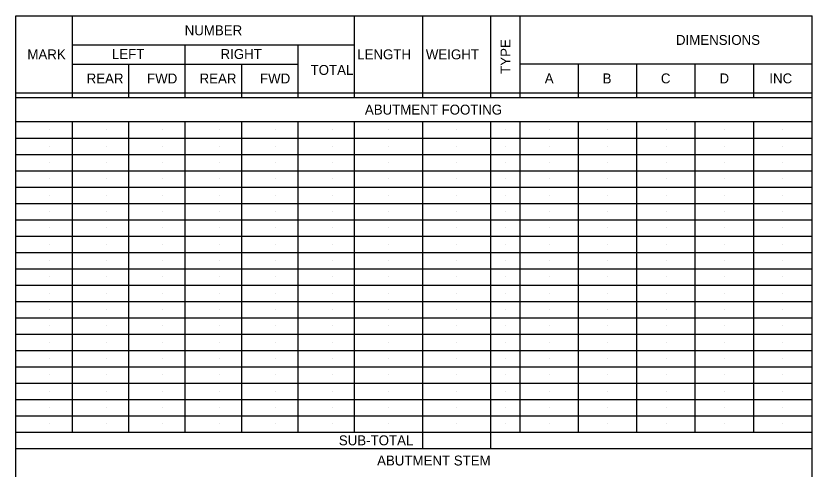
# Model space of a CAD drawing. Extents: x -18.5 to 33.3, y 0.6 to 37.5.
# Drawn here: x -18.5 to -4.86, y 12.95 to 20.71 of the extents above; entities that cross this region are included whole.
import ezdxf

# ---------------------------------------------------------------- set-up
doc = ezdxf.new("R2010")
doc.units = 0
doc.layers.add('BR_X_Beam_Centerline', color=7, linetype='Continuous')

msp = doc.modelspace()

# ---------------------------------------------------------------- linework, layer by layer
at = {"layer": 'BR_X_Beam_Centerline'}
for p, q in [((-18.496, 20.715), (-4.862, 20.715)), ((-18.496, 7.291), (-18.496, 20.715)), ((-17.529, 19.315), (-17.529, 20.715)), ((-12.696, 19.314), (-12.696, 20.715)), ((-11.529, 19.315), (-11.529, 20.715)), ((-10.362, 19.315), (-10.362, 20.715)), ((-9.862, 19.315), (-9.862, 20.715)), ((-4.862, 7.291), (-4.862, 20.715)), ((-17.529, 20.221), (-12.696, 20.221)), ((-15.596, 19.315), (-15.596, 20.221)), ((-13.662, 19.315), (-13.662, 20.221)), ((-17.529, 19.889), (-13.662, 19.888)), ((-16.563, 19.315), (-16.563, 19.889)), ((-14.629, 19.315), (-14.629, 19.888)), ((-9.862, 19.891), (-4.862, 19.891)), ((-8.862, 19.314), (-8.862, 19.891)), ((-7.862, 19.314), (-7.862, 19.891)), ((-6.862, 19.314), (-6.862, 19.891)), ((-5.862, 19.315), (-5.862, 19.891)), ((-5.862, 19.314), (-5.862, 19.891)), ((-16.946, 19.643), (-16.946, 19.643)), ((-15.979, 19.643), (-15.979, 19.643)), ((-15.012, 19.643), (-15.012, 19.643)), ((-14.046, 19.643), (-14.046, 19.643)), ((-18.496, 19.397), (-4.862, 19.397)), ((-18.496, 19.315), (-4.862, 19.315)), ((-11.279, 19.109), (-11.279, 19.109)), ((-18.496, 18.903), (-4.862, 18.903)), ((-17.529, 13.583), (-17.529, 18.903)), ((-16.562, 13.583), (-16.563, 18.903)), ((-15.596, 13.583), (-15.596, 18.903)), ((-14.629, 13.583), (-14.629, 18.903)), ((-13.662, 13.583), (-13.662, 18.903)), ((-12.696, 13.583), (-12.696, 18.903)), ((-11.529, 13.303), (-11.529, 18.903)), ((-10.362, 13.303), (-10.362, 18.903)), ((-9.862, 13.583), (-9.862, 18.903)), ((-8.862, 13.583), (-8.862, 18.903)), ((-7.862, 13.583), (-7.862, 18.903)), ((-6.862, 13.583), (-6.862, 18.903)), ((-5.862, 13.583), (-5.862, 18.903)), ((-5.862, 13.583), (-5.862, 18.903)), ((-17.913, 18.763), (-17.913, 18.763)), ((-16.946, 18.763), (-16.946, 18.763)), ((-15.979, 18.763), (-15.979, 18.763)), ((-15.012, 18.763), (-15.012, 18.763)), ((-14.046, 18.763), (-14.046, 18.763)), ((-13.079, 18.763), (-13.079, 18.763)), ((-12.112, 18.763), (-12.112, 18.763)), ((-10.946, 18.763), (-10.946, 18.763)), ((-10.112, 18.763), (-10.112, 18.763)), ((-9.362, 18.763), (-9.362, 18.763)), ((-8.362, 18.763), (-8.362, 18.763)), ((-7.362, 18.763), (-7.362, 18.763)), ((-6.362, 18.763), (-6.362, 18.763)), ((-5.362, 18.763), (-5.362, 18.763)), ((-18.496, 18.623), (-4.862, 18.623)), ((-17.913, 18.483), (-17.913, 18.483)), ((-16.946, 18.483), (-16.946, 18.483)), ((-15.979, 18.483), (-15.979, 18.483)), ((-15.012, 18.483), (-15.012, 18.483)), ((-14.046, 18.483), (-14.046, 18.483)), ((-13.079, 18.483), (-13.079, 18.483)), ((-12.112, 18.483), (-12.112, 18.483)), ((-10.946, 18.483), (-10.946, 18.483)), ((-10.112, 18.483), (-10.112, 18.483)), ((-9.362, 18.483), (-9.362, 18.483)), ((-8.362, 18.483), (-8.362, 18.483)), ((-7.362, 18.483), (-7.362, 18.483)), ((-6.362, 18.483), (-6.362, 18.483)), ((-5.362, 18.483), (-5.362, 18.483)), ((-18.496, 18.343), (-4.862, 18.343)), ((-17.913, 18.203), (-17.913, 18.203)), ((-16.946, 18.203), (-16.946, 18.203)), ((-15.979, 18.203), (-15.979, 18.203)), ((-15.012, 18.203), (-15.012, 18.203)), ((-14.046, 18.203), (-14.046, 18.203)), ((-13.079, 18.203), (-13.079, 18.203)), ((-12.112, 18.203), (-12.112, 18.203)), ((-10.946, 18.203), (-10.946, 18.203)), ((-10.112, 18.203), (-10.112, 18.203)), ((-9.362, 18.203), (-9.362, 18.203)), ((-8.362, 18.203), (-8.362, 18.203)), ((-7.362, 18.203), (-7.362, 18.203)), ((-6.362, 18.203), (-6.362, 18.203)), ((-5.362, 18.203), (-5.362, 18.203)), ((-18.496, 18.063), (-4.862, 18.063)), ((-17.913, 17.923), (-17.913, 17.923)), ((-16.946, 17.923), (-16.946, 17.923)), ((-15.979, 17.923), (-15.979, 17.923)), ((-15.012, 17.923), (-15.012, 17.923)), ((-14.046, 17.923), (-14.046, 17.923)), ((-13.079, 17.923), (-13.079, 17.923)), ((-12.112, 17.923), (-12.112, 17.923)), ((-10.946, 17.923), (-10.946, 17.923)), ((-10.112, 17.923), (-10.112, 17.923)), ((-9.362, 17.923), (-9.362, 17.923)), ((-8.362, 17.923), (-8.362, 17.923)), ((-7.362, 17.923), (-7.362, 17.923)), ((-6.362, 17.923), (-6.362, 17.923)), ((-5.362, 17.923), (-5.362, 17.923)), ((-18.496, 17.783), (-4.862, 17.783)), ((-17.913, 17.643), (-17.913, 17.643)), ((-16.946, 17.643), (-16.946, 17.643)), ((-15.979, 17.643), (-15.979, 17.643)), ((-15.012, 17.643), (-15.012, 17.643)), ((-14.046, 17.643), (-14.046, 17.643)), ((-13.079, 17.643), (-13.079, 17.643)), ((-12.112, 17.643), (-12.112, 17.643)), ((-10.946, 17.643), (-10.946, 17.643)), ((-10.112, 17.643), (-10.112, 17.643)), ((-9.362, 17.643), (-9.362, 17.643)), ((-8.362, 17.643), (-8.362, 17.643)), ((-7.362, 17.643), (-7.362, 17.643)), ((-6.362, 17.643), (-6.362, 17.643)), ((-5.362, 17.643), (-5.362, 17.643)), ((-18.496, 17.503), (-4.862, 17.503)), ((-17.913, 17.363), (-17.913, 17.363)), ((-16.946, 17.363), (-16.946, 17.363)), ((-15.979, 17.363), (-15.979, 17.363)), ((-15.012, 17.363), (-15.012, 17.363)), ((-14.046, 17.363), (-14.046, 17.363)), ((-13.079, 17.363), (-13.079, 17.363)), ((-12.112, 17.363), (-12.112, 17.363)), ((-10.946, 17.363), (-10.946, 17.363)), ((-10.112, 17.363), (-10.112, 17.363)), ((-9.362, 17.363), (-9.362, 17.363)), ((-8.362, 17.363), (-8.362, 17.363)), ((-7.362, 17.363), (-7.362, 17.363)), ((-6.362, 17.363), (-6.362, 17.363)), ((-5.362, 17.363), (-5.362, 17.363)), ((-18.496, 17.223), (-4.862, 17.223)), ((-17.913, 17.083), (-17.913, 17.083)), ((-16.946, 17.083), (-16.946, 17.083)), ((-15.979, 17.083), (-15.979, 17.083)), ((-15.012, 17.083), (-15.012, 17.083)), ((-14.046, 17.083), (-14.046, 17.083)), ((-13.079, 17.083), (-13.079, 17.083)), ((-12.112, 17.083), (-12.112, 17.083)), ((-10.946, 17.083), (-10.946, 17.083)), ((-10.112, 17.083), (-10.112, 17.083)), ((-9.362, 17.083), (-9.362, 17.083)), ((-8.362, 17.083), (-8.362, 17.083)), ((-7.362, 17.083), (-7.362, 17.083)), ((-6.362, 17.083), (-6.362, 17.083)), ((-5.362, 17.083), (-5.362, 17.083)), ((-18.496, 16.943), (-4.862, 16.943)), ((-17.913, 16.803), (-17.913, 16.803)), ((-16.946, 16.803), (-16.946, 16.803)), ((-15.979, 16.803), (-15.979, 16.803)), ((-15.012, 16.803), (-15.012, 16.803)), ((-14.046, 16.803), (-14.046, 16.803)), ((-13.079, 16.803), (-13.079, 16.803)), ((-12.112, 16.803), (-12.112, 16.803)), ((-10.946, 16.803), (-10.946, 16.803)), ((-10.112, 16.803), (-10.112, 16.803)), ((-9.362, 16.803), (-9.362, 16.803)), ((-8.362, 16.803), (-8.362, 16.803)), ((-7.362, 16.803), (-7.362, 16.803)), ((-6.362, 16.803), (-6.362, 16.803)), ((-5.362, 16.803), (-5.362, 16.803)), ((-18.496, 16.663), (-4.862, 16.663)), ((-17.913, 16.523), (-17.913, 16.523)), ((-16.946, 16.523), (-16.946, 16.523)), ((-15.979, 16.523), (-15.979, 16.523)), ((-15.012, 16.523), (-15.012, 16.523)), ((-14.046, 16.523), (-14.046, 16.523)), ((-13.079, 16.523), (-13.079, 16.523)), ((-12.112, 16.523), (-12.112, 16.523)), ((-10.946, 16.523), (-10.946, 16.523)), ((-10.112, 16.523), (-10.112, 16.523)), ((-9.362, 16.523), (-9.362, 16.523)), ((-8.362, 16.523), (-8.362, 16.523)), ((-7.362, 16.523), (-7.362, 16.523)), ((-6.362, 16.523), (-6.362, 16.523)), ((-5.362, 16.523), (-5.362, 16.523)), ((-18.496, 16.383), (-4.862, 16.383)), ((-17.913, 16.243), (-17.913, 16.243)), ((-16.946, 16.243), (-16.946, 16.243)), ((-15.979, 16.243), (-15.979, 16.243)), ((-15.012, 16.243), (-15.012, 16.243)), ((-14.046, 16.243), (-14.046, 16.243)), ((-13.079, 16.243), (-13.079, 16.243)), ((-12.112, 16.243), (-12.112, 16.243)), ((-10.946, 16.243), (-10.946, 16.243)), ((-10.112, 16.243), (-10.112, 16.243)), ((-9.362, 16.243), (-9.362, 16.243)), ((-8.362, 16.243), (-8.362, 16.243)), ((-7.362, 16.243), (-7.362, 16.243)), ((-6.362, 16.243), (-6.362, 16.243)), ((-5.362, 16.243), (-5.362, 16.243)), ((-18.496, 16.103), (-4.862, 16.103)), ((-17.913, 15.963), (-17.913, 15.963)), ((-16.946, 15.963), (-16.946, 15.963)), ((-15.979, 15.963), (-15.979, 15.963)), ((-15.012, 15.963), (-15.012, 15.963)), ((-14.046, 15.963), (-14.046, 15.963)), ((-13.079, 15.963), (-13.079, 15.963)), ((-12.112, 15.963), (-12.112, 15.963)), ((-10.946, 15.963), (-10.946, 15.963)), ((-10.112, 15.963), (-10.112, 15.963)), ((-9.362, 15.963), (-9.362, 15.963)), ((-8.362, 15.963), (-8.362, 15.963)), ((-7.362, 15.963), (-7.362, 15.963)), ((-6.362, 15.963), (-6.362, 15.963)), ((-5.362, 15.963), (-5.362, 15.963)), ((-18.496, 15.823), (-4.862, 15.823)), ((-17.913, 15.683), (-17.913, 15.683)), ((-16.946, 15.683), (-16.946, 15.683)), ((-15.979, 15.683), (-15.979, 15.683)), ((-15.012, 15.683), (-15.012, 15.683)), ((-14.046, 15.683), (-14.046, 15.683)), ((-13.079, 15.683), (-13.079, 15.683)), ((-12.112, 15.683), (-12.112, 15.683)), ((-10.946, 15.683), (-10.946, 15.683)), ((-10.112, 15.683), (-10.112, 15.683)), ((-9.362, 15.683), (-9.362, 15.683)), ((-8.362, 15.683), (-8.362, 15.683)), ((-7.362, 15.683), (-7.362, 15.683)), ((-6.362, 15.683), (-6.362, 15.683)), ((-5.362, 15.683), (-5.362, 15.683)), ((-18.496, 15.543), (-4.862, 15.543)), ((-17.913, 15.403), (-17.913, 15.403)), ((-16.946, 15.403), (-16.946, 15.403)), ((-15.979, 15.403), (-15.979, 15.403)), ((-15.012, 15.403), (-15.012, 15.403)), ((-14.046, 15.403), (-14.046, 15.403)), ((-13.079, 15.403), (-13.079, 15.403)), ((-12.112, 15.403), (-12.112, 15.403)), ((-10.946, 15.403), (-10.946, 15.403)), ((-10.112, 15.403), (-10.112, 15.403)), ((-9.362, 15.403), (-9.362, 15.403)), ((-8.362, 15.403), (-8.362, 15.403)), ((-7.362, 15.403), (-7.362, 15.403)), ((-6.362, 15.403), (-6.362, 15.403)), ((-5.362, 15.403), (-5.362, 15.403)), ((-18.496, 15.263), (-4.862, 15.263)), ((-17.913, 15.123), (-17.913, 15.123)), ((-16.946, 15.123), (-16.946, 15.123)), ((-15.979, 15.123), (-15.979, 15.123)), ((-15.012, 15.123), (-15.012, 15.123)), ((-14.046, 15.123), (-14.046, 15.123)), ((-13.079, 15.123), (-13.079, 15.123)), ((-12.112, 15.123), (-12.112, 15.123)), ((-10.946, 15.123), (-10.946, 15.123)), ((-10.112, 15.123), (-10.112, 15.123)), ((-9.362, 15.123), (-9.362, 15.123)), ((-8.362, 15.123), (-8.362, 15.123)), ((-7.362, 15.123), (-7.362, 15.123)), ((-6.362, 15.123), (-6.362, 15.123)), ((-5.362, 15.123), (-5.362, 15.123)), ((-18.496, 14.983), (-4.862, 14.983)), ((-17.913, 14.843), (-17.913, 14.843)), ((-16.946, 14.843), (-16.946, 14.843)), ((-15.979, 14.843), (-15.979, 14.843)), ((-15.012, 14.843), (-15.012, 14.843)), ((-14.046, 14.843), (-14.046, 14.843)), ((-13.079, 14.843), (-13.079, 14.843)), ((-12.112, 14.843), (-12.112, 14.843)), ((-10.946, 14.843), (-10.946, 14.843)), ((-10.112, 14.843), (-10.112, 14.843)), ((-9.362, 14.843), (-9.362, 14.843)), ((-8.362, 14.843), (-8.362, 14.843)), ((-7.362, 14.843), (-7.362, 14.843)), ((-6.362, 14.843), (-6.362, 14.843)), ((-5.362, 14.843), (-5.362, 14.843)), ((-18.496, 14.703), (-4.862, 14.703)), ((-17.913, 14.563), (-17.913, 14.563)), ((-16.946, 14.563), (-16.946, 14.563)), ((-15.979, 14.563), (-15.979, 14.563)), ((-15.012, 14.563), (-15.012, 14.563)), ((-14.046, 14.563), (-14.046, 14.563)), ((-13.079, 14.563), (-13.079, 14.563)), ((-12.112, 14.563), (-12.112, 14.563)), ((-10.946, 14.563), (-10.946, 14.563)), ((-10.112, 14.563), (-10.112, 14.563)), ((-9.362, 14.563), (-9.362, 14.563)), ((-8.362, 14.563), (-8.362, 14.563)), ((-7.362, 14.563), (-7.362, 14.563)), ((-6.362, 14.563), (-6.362, 14.563)), ((-5.362, 14.563), (-5.362, 14.563)), ((-18.496, 14.423), (-4.862, 14.423)), ((-17.913, 14.283), (-17.913, 14.283)), ((-16.946, 14.283), (-16.946, 14.283)), ((-15.979, 14.283), (-15.979, 14.283)), ((-15.012, 14.283), (-15.012, 14.283)), ((-14.046, 14.283), (-14.046, 14.283)), ((-13.079, 14.283), (-13.079, 14.283)), ((-12.112, 14.283), (-12.112, 14.283)), ((-10.946, 14.283), (-10.946, 14.283)), ((-10.112, 14.283), (-10.112, 14.283)), ((-9.362, 14.283), (-9.362, 14.283)), ((-8.362, 14.283), (-8.362, 14.283)), ((-7.362, 14.283), (-7.362, 14.283)), ((-6.362, 14.283), (-6.362, 14.283)), ((-5.362, 14.283), (-5.362, 14.283)), ((-18.496, 14.143), (-4.862, 14.143)), ((-17.913, 14.003), (-17.913, 14.003)), ((-16.946, 14.003), (-16.946, 14.003)), ((-15.979, 14.003), (-15.979, 14.003)), ((-15.012, 14.003), (-15.012, 14.003)), ((-14.046, 14.003), (-14.046, 14.003)), ((-13.079, 14.003), (-13.079, 14.003)), ((-12.112, 14.003), (-12.112, 14.003)), ((-10.946, 14.003), (-10.946, 14.003)), ((-10.112, 14.003), (-10.112, 14.003)), ((-9.362, 14.003), (-9.362, 14.003)), ((-8.362, 14.003), (-8.362, 14.003)), ((-7.362, 14.003), (-7.362, 14.003)), ((-6.362, 14.003), (-6.362, 14.003)), ((-5.362, 14.003), (-5.362, 14.003)), ((-18.496, 13.863), (-4.862, 13.863)), ((-17.913, 13.723), (-17.913, 13.723)), ((-16.946, 13.723), (-16.946, 13.723)), ((-15.979, 13.723), (-15.979, 13.723)), ((-15.012, 13.723), (-15.012, 13.723)), ((-14.046, 13.723), (-14.046, 13.723)), ((-13.079, 13.723), (-13.079, 13.723)), ((-12.112, 13.723), (-12.112, 13.723)), ((-10.946, 13.723), (-10.946, 13.723)), ((-10.112, 13.723), (-10.112, 13.723)), ((-9.362, 13.723), (-9.362, 13.723)), ((-8.362, 13.723), (-8.362, 13.723)), ((-7.362, 13.723), (-7.362, 13.723)), ((-6.362, 13.723), (-6.362, 13.723)), ((-5.362, 13.723), (-5.362, 13.723)), ((-18.496, 13.583), (-4.862, 13.583)), ((-18.496, 13.303), (-4.862, 13.303)), ((-11.279, 13.097), (-11.279, 13.097))]:
    msp.add_line(p, q, dxfattribs=at)

# ---------------------------------------------------------------- texts
for s, p in [('NUMBER', (-15.606, 20.383)), ('DIMENSIONS', (-7.193, 20.218)), ('MARK', (-18.3, 19.971)), ('LEFT', (-16.853, 19.977)), ('RIGHT', (-14.992, 19.977)), ('LENGTH', (-12.652, 19.971)), ('WEIGHT', (-11.476, 19.971)), ('TOTAL', (-13.45, 19.704)), ('REAR', (-17.285, 19.558)), ('FWD', (-16.25, 19.558)), ('REAR', (-15.351, 19.558)), ('FWD', (-14.316, 19.558)), ('A', (-9.44, 19.559)), ('B', (-8.449, 19.559)), ('C', (-7.451, 19.559)), ('D', (-6.447, 19.559)), ('INC', (-5.594, 19.559)), ('ABUTMENT FOOTING', (-12.52, 19.024)), ('SUB-TOTAL', (-12.966, 13.358)), ('ABUTMENT STEM', (-12.311, 13.012))]:
    msp.add_text(s, height=0.17, dxfattribs=at).set_placement(p)
msp.add_text('TYPE', height=0.17, rotation=90, dxfattribs=at).set_placement((-10.027, 19.722))

doc.saveas('drawing.dxf')
